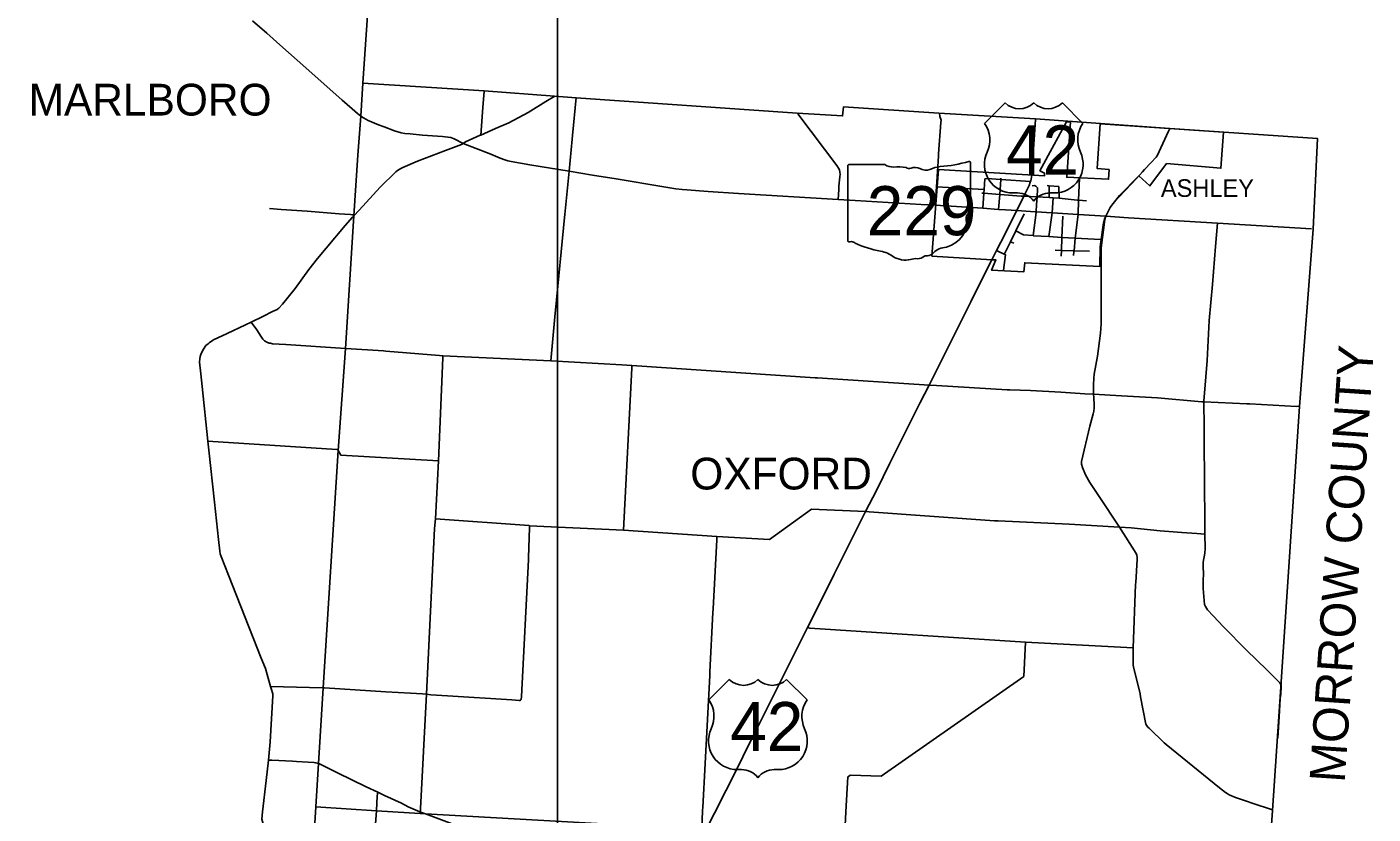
# Model space of a CAD drawing. Extents: x 1729596 to 1925846, y 659247 to 911751.
# Drawn here: x 1813555 to 1851720, y 860705 to 883019 of the extents above; entities that cross this region are included whole.
import ezdxf

# ---------------------------------------------------------------- set-up
doc = ezdxf.new("R2010")
doc.units = 0
for name, color, linetype in [('GM_X_Adjacent_County_Text', 7, 'Continuous'), ('GM_X_City_Street', 7, 'Continuous'), ('GM_X_Corporation', 7, 'Continuous'), ('GM_X_Corporation_Text', 7, 'Continuous'), ('GM_X_County', 7, 'Continuous'), ('GM_X_County_Road', 7, 'Continuous'), ('GM_X_State_Route', 7, 'Continuous'), ('GM_X_State_Shield', 7, 'Continuous'), ('GM_X_Township', 7, 'Continuous'), ('GM_X_Township_Road', 7, 'Continuous'), ('GM_X_Township_Text', 7, 'Continuous'), ('GM_X_US_Route', 7, 'Continuous'), ('GM_X_US_Shield', 7, 'Continuous'), ('SH_Data', 7, 'Continuous')]:
    doc.layers.add(name, color=color, linetype=linetype)

msp = doc.modelspace()

# ---------------------------------------------------------------- linework, layer by layer
at = {"layer": 'GM_X_City_Street'}
for points in [[(1845108, 878825), (1845186, 878908), (1845242, 878975), (1845432, 879171), (1845571, 879323), (1845601, 879368), (1845923, 880061), (1845958, 880137)], [(1840655, 877877), (1840684, 878302), (1840692, 878411), (1840712, 878711)], [(1840712, 878711), (1840771, 878720), (1841162, 878693), (1842005, 878635)], [(1841096, 877846), (1841141, 878272), (1841162, 878693), (1841165, 878729)], [(1843359, 877702), (1843365, 878107), (1843394, 878741)], [(1839341, 878485), (1840692, 878411)], [(1840624, 878310), (1840684, 878302), (1841141, 878272), (1841739, 878225)], [(1841739, 878225), (1841815, 878219), (1842196, 878198), (1842538, 878180), (1842649, 878172), (1842823, 878163), (1843332, 878109)], [(1842195, 878194), (1842196, 878198), (1842207, 878423), (1842204, 878453), (1842189, 878476), (1842156, 878505), (1842118, 878523), (1842051, 878515)], [(1842164, 877756), (1842167, 877780), (1842180, 877986), (1842195, 878194)], [(1842480, 878523), (1842536, 878518), (1842809, 878492)], [(1842538, 878180), (1842536, 878518)], [(1842823, 878163), (1842809, 878492)], [(1842531, 877075), (1842621, 877751), (1842649, 878172)], [(1843332, 878109), (1843335, 878108), (1843365, 878107), (1843598, 878093)], [(1841290, 876572), (1841275, 876591), (1841439, 876928), (1841591, 877241), (1841826, 877723)], [(1842082, 877102), (1842164, 877756)], [(1842882, 876677), (1842882, 876677), (1842882, 876684), (1842900, 877054), (1842928, 877653)], [(1843238, 876648), (1843241, 876673), (1843277, 877031), (1843359, 877702)], [(1841591, 877241), (1841805, 877127), (1842082, 877102), (1842094, 877101), (1842531, 877075), (1842900, 877054), (1843277, 877031), (1843995, 876989)], [(1841039, 876677), (1841303, 876558)], [(1841439, 876928), (1841534, 876885)], [(1842709, 876689), (1842882, 876684), (1843220, 876674), (1843220, 876674)], [(1842875, 876522), (1842882, 876677)], [(1843220, 876674), (1843241, 876673), (1843680, 876660)], [(1841244, 876119), (1841303, 876558), (1841290, 876572)], [(1843230, 876537), (1843238, 876642), (1843238, 876648)]]:
    msp.add_lwpolyline(points, dxfattribs=at)
at = {"layer": 'GM_X_Corporation'}
msp.add_lwpolyline([(1839212, 876522), (1839395, 878979), (1842403, 878797), (1842406, 878874), (1842276, 878944), (1843026, 880333), (1843137, 880326), (1843037, 878758), (1844222, 878701), (1844237, 878976), (1843894, 879006), (1843983, 880269), (1847478, 880034), (1847407, 879013), (1845866, 879149), (1845394, 878513), (1845080, 878796), (1844533, 878238), (1844393, 878064), (1844314, 877970), (1844271, 877898), (1844236, 877846), (1844178, 877730), (1844140, 877653), (1844101, 877578), (1844075, 877468), (1843989, 876865), (1843985, 876781), (1843972, 876227), (1841843, 876336), (1841816, 876073), (1840902, 876121), (1841027, 876414), (1840914, 876421)], close=True, dxfattribs=at)
at = {"layer": 'GM_X_County'}
msp.add_lwpolyline([(1813443, 887429), (1813717, 887422), (1814360, 887388), (1814847, 887358), (1815353, 887328), (1818316, 887169), (1823458, 886911), (1823082, 881429), (1826517, 881205), (1828513, 881052), (1829123, 881005), (1835395, 880574), (1836682, 880495), (1836708, 880754), (1839410, 880574), (1842150, 880416), (1845959, 880135), (1850147, 879854), (1850017, 877290), (1849634, 872258), (1849106, 864311), (1848864, 860810), (1848787, 859601)], dxfattribs=at)
at = {"layer": 'GM_X_County_Road'}
for points in [[(1826404, 879946), (1826423, 879954), (1826844, 880138), (1827215, 880304), (1827767, 880596), (1828264, 880901), (1828526, 881056)], [(1826423, 879954), (1826479, 880739), (1826518, 881195)], [(1822822, 877662), (1822979, 877822), (1823573, 878476), (1824013, 878909), (1824059, 878945), (1824151, 879002), (1824217, 879033), (1824631, 879211), (1825422, 879515), (1825871, 879688), (1825923, 879717)], [(1825923, 879717), (1825991, 879759), (1826404, 879946)], [(1844140, 877653), (1844178, 877730), (1844236, 877846), (1844271, 877898), (1844314, 877970), (1844393, 878064), (1844672, 878363), (1844876, 878580), (1845108, 878825)], [(1818695, 874040), (1818726, 874065), (1818820, 874127), (1818849, 874146), (1819230, 874331), (1819753, 874577), (1819917, 874653), (1820258, 874816), (1820515, 874948), (1820647, 875011), (1820694, 875046), (1820805, 875160), (1821161, 875608), (1821552, 876138), (1821797, 876450), (1822043, 876750), (1822580, 877393), (1822787, 877627), (1822822, 877662)], [(1844920, 865421), (1844988, 867215), (1844990, 867274), (1845035, 867925), (1845034, 867981), (1845022, 868042), (1845000, 868095), (1844527, 868834), (1843932, 869740), (1843693, 870106), (1843565, 870325), (1843478, 870530), (1843453, 870621), (1843455, 870702), (1843691, 871703), (1843783, 872054), (1843799, 872125), (1843808, 872218), (1843813, 872294), (1843800, 872513), (1843796, 872610), (1843794, 872719), (1843797, 872872), (1843799, 873058), (1843810, 873171), (1843903, 873683), (1843995, 874339), (1844011, 874603), (1844010, 875790), (1844011, 876128), (1844012, 876758), (1844119, 877561), (1844140, 877653)], [(1820462, 864324), (1820315, 864828), (1820199, 865126), (1819267, 867478), (1819059, 868009), (1819037, 868087), (1819024, 868161), (1818988, 868490), (1818871, 869545), (1818714, 871024), (1818688, 871275), (1818522, 872824), (1818481, 873185), (1818449, 873518), (1818456, 873613), (1818468, 873675), (1818498, 873766), (1818559, 873888), (1818627, 873984), (1818695, 874040)], [(1824699, 860768), (1824709, 860807), (1824715, 860860), (1824883, 864100), (1825114, 868796), (1825134, 869072), (1825228, 870716), (1825347, 873642), (1825350, 873697)], [(1825350, 873697), (1828404, 873550), (1830426, 873436), (1830706, 873421), (1835899, 873073), (1835968, 873069), (1839135, 872864)], [(1839135, 872864), (1839344, 872852), (1841345, 872730), (1841421, 872727), (1842003, 872716), (1842870, 872667), (1843552, 872620), (1843796, 872610)], [(1848869, 860822), (1848289, 861017), (1848127, 861070), (1847820, 861177), (1847644, 861252), (1847581, 861290), (1847540, 861317), (1847370, 861450), (1845855, 862679), (1845795, 862727), (1845378, 863132), (1845338, 863172), (1845282, 863256), (1845130, 864033), (1845116, 864109), (1844927, 864878), (1844914, 864930), (1844919, 865353), (1844920, 865421)], [(1819979, 856052), (1820004, 856221), (1820093, 856849), (1820106, 856948), (1820253, 859267), (1820256, 859321), (1820308, 860164), (1820312, 860243), (1820295, 860293), (1820272, 860358), (1820219, 860562), (1820238, 860767), (1820341, 861658), (1820408, 862232), (1820454, 862755), (1820524, 864057), (1820528, 864114), (1820480, 864265), (1820462, 864324)], [(1820408, 862232), (1820494, 862231), (1821085, 862203), (1821196, 862192), (1821533, 862179), (1821692, 862169), (1821732, 862161)], [(1821732, 862161), (1821747, 862158), (1821783, 862149), (1821820, 862138), (1821852, 862127), (1822363, 861870), (1822764, 861678), (1823175, 861477), (1823506, 861322), (1823697, 861236), (1824174, 861011), (1824367, 860911), (1824699, 860768)], [(1824699, 860768), (1824857, 860710), (1825612, 860430), (1826656, 860059), (1826853, 859982), (1826971, 859934), (1827258, 859768), (1827710, 859527), (1828254, 859247), (1828432, 859153), (1828513, 859123), (1828584, 859112), (1829052, 859088), (1829917, 859051), (1830145, 859048), (1831204, 858991), (1831412, 858982), (1831846, 858956), (1831978, 858953), (1832140, 858950)]]:
    msp.add_lwpolyline(points, dxfattribs=at)
at = {"layer": 'GM_X_State_Route'}
for points in [[(1819954, 883190), (1820355, 882842), (1820806, 882440), (1821377, 881933), (1822496, 880940), (1822775, 880699), (1822923, 880569), (1823026, 880489), (1823096, 880443), (1823229, 880369), (1823524, 880245), (1823681, 880185), (1823974, 880072), (1824071, 880043), (1824169, 880019), (1824269, 880002), (1824418, 879984), (1824766, 879955), (1825340, 879913), (1825491, 879897), (1825574, 879880), (1825668, 879848), (1825923, 879717), (1826289, 879572), (1826707, 879409), (1826973, 879302), (1827103, 879251), (1827193, 879225), (1827284, 879205), (1827814, 879113), (1828926, 878930), (1829588, 878819), (1830263, 878712), (1831616, 878486), (1831957, 878431), (1832136, 878410), (1832267, 878397), (1832870, 878356), (1833733, 878300), (1836550, 878131), (1837033, 878098), (1838904, 877988), (1839306, 877964)], [(1839306, 877964), (1840655, 877877), (1841096, 877846), (1841303, 877834)], [(1841303, 877834), (1841619, 877817)], [(1841619, 877817), (1842011, 877788), (1842144, 877781)], [(1842144, 877781), (1842167, 877780), (1842611, 877751), (1842621, 877751), (1843359, 877702), (1844140, 877653)], [(1844140, 877653), (1844783, 877609), (1847310, 877457), (1849978, 877293)]]:
    msp.add_lwpolyline(points, dxfattribs=at)
at = {"layer": 'GM_X_State_Shield'}
for p, q in [((1836826, 879078), (1836826, 876965)), ((1836826, 879078), (1836826, 876965)), ((1837880, 879115), (1836860, 879115)), ((1837880, 879115), (1836860, 879115)), ((1840307, 878062), (1840307, 879167)), ((1840307, 878062), (1840307, 879167)), ((1840306, 878062), (1840307, 878062)), ((1840306, 878062), (1840307, 878062))]:
    msp.add_line(p, q, dxfattribs=at)
for centre, major_axis, start_param, end_param in [((1836866, 879083), (40.3, 0), 1.712693, 3.28349), ((1836866, 879083), (40.3, 0), 1.712693, 3.28349), ((1838122, 879360), (391, 0), 4.042523, 4.731795), ((1838122, 879360), (391, 0), 4.042523, 4.731795), ((1838252, 877928), (1404, 0), 1.404758, 1.657858), ((1838252, 877928), (1404, 0), 1.404758, 1.657858), ((1838571, 879094), (113, 0), 3.836095, 5.185415), ((1838571, 879094), (113, 0), 3.836095, 5.185415), ((1838736, 878850), (235, 0), 0.950623, 2.079405), ((1838736, 878850), (235, 0), 0.950623, 2.079405), ((1839039, 879185), (282, 0), 4.081561, 5.145723), ((1839039, 879185), (282, 0), 4.081561, 5.145723), ((1839538, 878469), (743, 0), 1.699011, 2.107814), ((1839538, 878469), (743, 0), 1.699011, 2.107814), ((1839067, 881996), (3691, 0), 4.814394, 5.042369), ((1839067, 881996), (3691, 0), 4.814394, 5.042369), ((1840268, 879172), (38.7, 0), 6.141152, 7.989035), ((1840268, 879172), (38.7, 0), 6.141152, 7.989035), ((1840298, 877981), (60, 0), 1.883978, 3.671073), ((1840298, 877981), (60, 0), 1.883978, 3.671073), ((1839916, 877841), (360, 0), 5.934695, 6.695948), ((1839916, 877841), (360, 0), 5.934695, 6.695948), ((1840265, 878057), (41.5, 0), 5.05454, 6.418171), ((1840265, 878057), (41.5, 0), 5.05454, 6.418171), ((1839274, 877458), (923, 0), 5.101752, 6.440018), ((1839274, 877458), (923, 0), 5.101752, 6.440018), ((1840445, 877599), (262, 0), 2.387724, 3.262537), ((1840445, 877599), (262, 0), 2.387724, 3.262537), ((1836866, 876961), (40.7, 0), 3.00124, 4.508301), ((1836866, 876961), (40.7, 0), 3.00124, 4.508301), ((1836873, 877177), (310, 0), 4.665946, 4.897461), ((1836873, 877177), (310, 0), 4.665946, 4.897461), ((1836936, 876843), (112, 0), 0.519207, 1.627899), ((1836936, 876843), (112, 0), 0.519207, 1.627899), ((1838349, 878742), (2665, 0), 4.195997, 4.488961), ((1838349, 878742), (2665, 0), 4.195997, 4.488961), ((1837555, 876016), (834, 0), 0.823519, 1.323587), ((1837555, 876016), (834, 0), 0.823519, 1.323587), ((1839663, 876372), (506, 0), 1.647645, 2.488434), ((1839663, 876372), (506, 0), 1.647645, 2.488434), ((1838457, 876833), (529, 0), 4.026481, 4.996735), ((1838457, 876833), (529, 0), 4.026481, 4.996735), ((1838762, 876102), (435, 0), 1.495662, 1.94098), ((1838762, 876102), (435, 0), 1.495662, 1.94098), ((1838801, 876675), (282, 0), 4.691044, 5.507374), ((1838801, 876675), (282, 0), 4.691044, 5.507374), ((1839056, 876470), (79.4, 0), 1.147584, 2.315152), ((1839056, 876470), (79.4, 0), 1.147584, 2.315152), ((1839022, 876760), (298, 0), 4.937069, 5.64225), ((1839022, 876760), (298, 0), 4.937069, 5.64225)]:
    msp.add_ellipse(centre, major_axis=major_axis, ratio=0.8, start_param=start_param, end_param=end_param, dxfattribs=at)
at = {"layer": 'GM_X_Township'}
for points in [[(1830057, 860416), (1824857, 860710), (1823464, 860801), (1821743, 860915), (1821820, 862138), (1821956, 864281), (1822382, 871013), (1822583, 873901), (1822822, 877662), (1822932, 879384), (1823026, 880489), (1823082, 881429)], [(1850147, 879854), (1850017, 877290), (1849634, 872258), (1849106, 864311), (1848864, 860810), (1848787, 859601)], [(1820182, 834021), (1820274, 835623), (1820357, 837080), (1820411, 838018), (1820789, 844650), (1820950, 847472), (1821204, 851968), (1821306, 853784), (1821743, 860915)]]:
    msp.add_lwpolyline(points, dxfattribs=at)
at = {"layer": 'GM_X_Township_Road'}
for points in [[(1828926, 878930), (1829014, 879840), (1829023, 879943), (1829130, 881016)], [(1836550, 878131), (1836572, 878407), (1836577, 878507), (1836605, 878769), (1836613, 878847), (1836605, 878899), (1836595, 878967), (1836565, 879011), (1836515, 879086), (1835436, 880521), (1835397, 880584)], [(1839306, 877964), (1839341, 878485), (1839399, 879352), (1839403, 879417), (1839467, 880312), (1839471, 880374), (1839440, 880475), (1839429, 880574)], [(1828404, 873550), (1828535, 874900), (1828545, 874985), (1828797, 877614), (1828805, 877701), (1828926, 878930)], [(1820435, 877874), (1820766, 877848), (1821496, 877793), (1822410, 877722), (1822732, 877701), (1822772, 877694), (1822797, 877688), (1822822, 877662)], [(1846952, 868642), (1846950, 869189), (1846940, 869904), (1846940, 870264), (1846936, 871157), (1846927, 871876), (1846924, 872189), (1846924, 872391), (1846924, 872409), (1846974, 873096), (1847017, 873560), (1847077, 874700), (1847167, 875719), (1847252, 876799), (1847310, 877457)], [(1819917, 874653), (1820070, 874430), (1820190, 874250), (1820246, 874169), (1820290, 874124), (1820359, 874086), (1820425, 874058), (1820460, 874051)], [(1820460, 874051), (1820518, 874039), (1820891, 874015), (1822583, 873901), (1822593, 873900)], [(1822593, 873900), (1823661, 873833), (1823727, 873829), (1825253, 873705), (1825350, 873697)], [(1830464, 868756), (1830701, 873344), (1830706, 873421)], [(1843796, 872610), (1844591, 872563), (1845606, 872508), (1846865, 872395), (1846924, 872391), (1848139, 872336), (1848226, 872331), (1849545, 872262), (1849640, 872268)], [(1818688, 871275), (1822342, 871039), (1822367, 871038)], [(1822367, 871038), (1822368, 871038), (1822382, 871013), (1822458, 870878), (1825228, 870716)], [(1825134, 869072), (1827790, 868881), (1827808, 868880), (1830464, 868756), (1833115, 868570), (1834606, 868488), (1835796, 869350), (1837331, 869279), (1837434, 869271)], [(1837434, 869271), (1840984, 869021), (1841014, 869019), (1841088, 869014), (1843104, 868927), (1844527, 868834), (1844860, 868817), (1845680, 868730), (1846299, 868685), (1846723, 868656), (1846952, 868642)], [(1824883, 864100), (1825008, 864087), (1825479, 864057), (1827301, 863943), (1827512, 863928), (1827528, 863927), (1827544, 863932), (1827556, 863942), (1827563, 863956), (1827574, 864035), (1827772, 867912), (1827777, 867978), (1827806, 868822), (1827808, 868880)], [(1832712, 860086), (1832692, 860180), (1832694, 860243), (1832711, 860815), (1832717, 860894), (1832916, 864638), (1832920, 864735), (1833003, 866422), (1833008, 866525), (1833111, 868476), (1833115, 868570)], [(1847190, 866322), (1847029, 866494), (1846966, 866586), (1846940, 866643), (1846902, 867096), (1846899, 867328), (1846913, 867520), (1846901, 867711), (1846907, 867849), (1846949, 868098), (1846958, 868238), (1846952, 868642)], [(1835681, 865996), (1835751, 865973), (1841870, 865582), (1844920, 865421)], [(1849108, 864379), (1849086, 864409), (1849077, 864422), (1849056, 864444), (1848707, 864795), (1848132, 865354), (1847476, 866016), (1847190, 866322)], [(1836801, 859906), (1836785, 859928), (1836730, 860003), (1836772, 860771), (1836832, 861759), (1836900, 861806), (1837774, 861777), (1841815, 864609), (1841870, 865582)], [(1820462, 864324), (1821937, 864282)], [(1821937, 864282), (1821956, 864281), (1821991, 864279), (1823727, 864175), (1824431, 864135), (1824774, 864114), (1824883, 864100)], [(1849021, 862856), (1849057, 863463), (1849090, 863978), (1849102, 864092), (1849117, 864321), (1849117, 864329), (1849117, 864338), (1849117, 864343), (1849117, 864351), (1849116, 864355), (1849116, 864358), (1849115, 864361), (1849113, 864368), (1849111, 864373), (1849108, 864379)], [(1823464, 860797), (1823464, 860801), (1823489, 861218), (1823506, 861322)], [(1822973, 852697), (1823090, 854855), (1823095, 854950), (1823360, 859378), (1823364, 859462), (1823464, 860797)]]:
    msp.add_lwpolyline(points, dxfattribs=at)
at = {"layer": 'GM_X_US_Route'}
for points in [[(1842050, 878929), (1842054, 878989), (1842074, 879275), (1842125, 879970), (1842151, 880391)], [(1841619, 877817), (1841815, 878219), (1841969, 878528), (1842000, 878620)], [(1842000, 878620), (1842005, 878635), (1842013, 878659), (1842035, 878764), (1842042, 878816), (1842050, 878929)], [(1841285, 877158), (1841355, 877293), (1841619, 877817)], [(1840905, 876404), (1840914, 876421), (1841039, 876677), (1841285, 877158)], [(1832814, 860270), (1833045, 860728), (1833707, 862039), (1833995, 862623), (1834269, 863162), (1835215, 865051), (1835681, 865996), (1836078, 866774), (1836442, 867502), (1837331, 869279), (1837642, 869882), (1838022, 870648), (1838475, 871555), (1838873, 872351), (1839135, 872864), (1840316, 875226), (1840905, 876404)]]:
    msp.add_lwpolyline(points, dxfattribs=at)
at = {"layer": 'GM_X_US_Shield'}
for p, q in [((1841287, 880866), (1840707, 880285)), ((1841287, 880866), (1840707, 880285)), ((1843491, 880285), (1842911, 880866)), ((1843491, 880285), (1842911, 880866)), ((1841519, 878313), (1841635, 878313)), ((1841519, 878313), (1841635, 878313)), ((1842563, 878313), (1842679, 878313)), ((1842563, 878313), (1842679, 878313)), ((1833468, 864520), (1832888, 863940)), ((1833468, 864520), (1832888, 863940)), ((1835673, 863940), (1835092, 864520)), ((1835673, 863940), (1835092, 864520)), ((1833700, 861967), (1833816, 861967)), ((1833700, 861967), (1833816, 861967)), ((1834744, 861967), (1834860, 861967)), ((1834744, 861967), (1834860, 861967))]:
    msp.add_line(p, q, dxfattribs=at)
for centre, radius, start, end in [((1841693, 881280), 580, 225.573, 314.427), ((1841693, 881280), 580, 225.573, 314.427), ((1842505, 881280), 580, 225.573, 314.427), ((1842505, 881280), 580, 225.573, 314.427), ((1840042, 879820), 812, 334.5471, 35.0009), ((1840042, 879820), 812, 334.5471, 35.0009), ((1844157, 879820), 812, 144.9991, 205.4529), ((1844157, 879820), 812, 144.9991, 205.4529), ((1841510, 879125), 812, 154.8319, 270.6383), ((1841510, 879125), 812, 154.8319, 270.6383), ((1842688, 879125), 812, 269.3617, 25.1681), ((1842688, 879125), 812, 269.3617, 25.1681), ((1841635, 877733), 580, 36.8699, 90), ((1841635, 877733), 580, 36.8699, 90), ((1842563, 877733), 580, 90, 143.1301), ((1842563, 877733), 580, 90, 143.1301), ((1833874, 864934), 580, 225.573, 314.427), ((1833874, 864934), 580, 225.573, 314.427), ((1834686, 864934), 580, 225.573, 314.427), ((1834686, 864934), 580, 225.573, 314.427), ((1832223, 863474), 812, 334.5471, 35.0009), ((1832223, 863474), 812, 334.5471, 35.0009), ((1836338, 863474), 812, 144.9991, 205.4529), ((1836338, 863474), 812, 144.9991, 205.4529), ((1833691, 862779), 812, 154.8319, 270.6383), ((1833691, 862779), 812, 154.8319, 270.6383), ((1834869, 862779), 812, 269.3617, 25.1681), ((1834869, 862779), 812, 269.3617, 25.1681), ((1833816, 861387), 580, 36.8699, 90), ((1833816, 861387), 580, 36.8699, 90), ((1834744, 861387), 580, 90, 143.1301), ((1834744, 861387), 580, 90, 143.1301)]:
    msp.add_arc(centre, radius, start, end, dxfattribs=at)
at = {"layer": 'SH_Data'}
msp.add_line((1828599, 890928), (1828599, 814428), dxfattribs=at)

# ---------------------------------------------------------------- texts
at = {"layer": 'GM_X_Adjacent_County_Text'}
msp.add_text('MORROW COUNTY', height=1000, rotation=86.16, dxfattribs=at).set_placement((1850915, 861578))
at = {"layer": 'GM_X_Corporation_Text'}
msp.add_text('ASHLEY', height=500, rotation=0, dxfattribs=at).set_placement((1845704, 878201))
at = {"layer": 'GM_X_State_Shield'}
msp.add_text('229', height=1392.2, dxfattribs=at).set_placement((1837366, 877114))
msp.add_text('229', height=1392.2, dxfattribs=at).set_placement((1837366, 877114))
at = {"layer": 'GM_X_Township_Text'}
for s, p in [('MARLBORO', (1813603, 880507)), ('OXFORD', (1832362, 869907))]:
    msp.add_text(s, height=900, rotation=0, dxfattribs=at).set_placement(p)
at = {"layer": 'GM_X_US_Shield'}
for p in [(1841315, 878835), (1841315, 878835), (1833497, 862489), (1833497, 862489)]:
    msp.add_text('42', height=1392.2, dxfattribs=at).set_placement(p)

doc.saveas('drawing.dxf')
